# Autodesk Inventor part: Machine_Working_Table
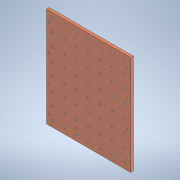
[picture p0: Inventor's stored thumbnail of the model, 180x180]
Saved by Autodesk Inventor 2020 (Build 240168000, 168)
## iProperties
Created: 2020-02
Part Number: Machine_Working_Table
Material: Generic
Document SubType Name: Modeling
Designer: mmg
Density: 1 g/cm^3
Appearance: Default
Author: mmg
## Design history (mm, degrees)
sketch "Sketch1"
  geometry: L1 (0, 0)-(527, 0); L2 (527, 0)-(527, 624); L3 (527, 624)-(0, 624); L4 (0, 624)-(0, 0)
  constraints: 8 end point, 2 parallel, 1 horizontal, 1 perpendicular
  dimensions: "d0" = 527 distance of L3.end L2.end; "d1" = 624 distance of L2.end L1.end
extrude "Extrusion1" new body sketch "Sketch1" distance "d2" = 16.5 (= Thickness); taper "d3" = 0 deg
sketch "Sketch2"
  geometry: L1 (0, 624)-(0, 0) reference; L2 (0, 0)-(527, 0) reference; 1 further point
  dimensions: "d11" = 14.5 distance from line of L1 point (14.5, 64.5); "d12" = 64.5 distance from line of L2 point (14.5, 64.5)
hole "Hole1" sketch "Sketch2" at (14.5, 64.5) diameter "d4" = 9; stored, may be unused: countersink angle "d8" = 90 deg, drill point angle "d10" = 118 deg; dims "d5" = 6, "d6" = 4, "d7" = 2, "d9" = 8
pattern_linear "Rectangular Pattern1" dims "d15" = 165, "d18" = 498
sketch "Sketch3"
  geometry: L1 (0, 624)-(0, 0) reference; L2 (0, 0)-(527, 0) reference; 1 further point
  dimensions: "d19" = 38.5 distance from line of L1 point (38.5, 37); "d20" = 37 distance from line of L2 point (38.5, 37)
hole "Hole2" sketch "Sketch3" at (38.5, 37) diameter "d21" = 9.7 (= diameter_bolt); stored, may be unused: countersink angle "d25" = 90 deg, drill point angle "d27" = 118 deg; dims "d22" = 6, "d23" = 4, "d24" = 2, "d26" = 8
sketch "Sketch4"
  geometry: C1 r 4.85 at (-38.5, 37) reference; C2 r 12.5 at (-38.5, 37); 1 further point
  constraints: 1 centre point, 1 coincident
  dimensions: "d34" = 25 diameter of C2 (= Outer_dia_bolt)
extrude "Extrusion2" cut sketch "Sketch4" distance "d35" = 3 (= bolt_height); taper "d36" = 0 deg
pattern_linear "Rectangular Pattern4" dims "d45" = 166
pattern_linear "Rectangular Pattern5" dims "d48" = 495
body "Solid1"
pattern_linear "Rectangular Pattern2" dims "d30" = 75, "d33" = 80
pattern_linear "Rectangular Pattern3" dims "d39" = 80, "d42" = 75
other parameters: "Thickness" = 16.5 [user parameter; used in 1 equation term], "diameter_bolt" = 9.7 [user parameter; used in 1 equation term], "bolt_height" = 3 [user parameter; used in 1 equation term], "Outer_dia_bolt" = 25 [user parameter; used in 1 equation term]
